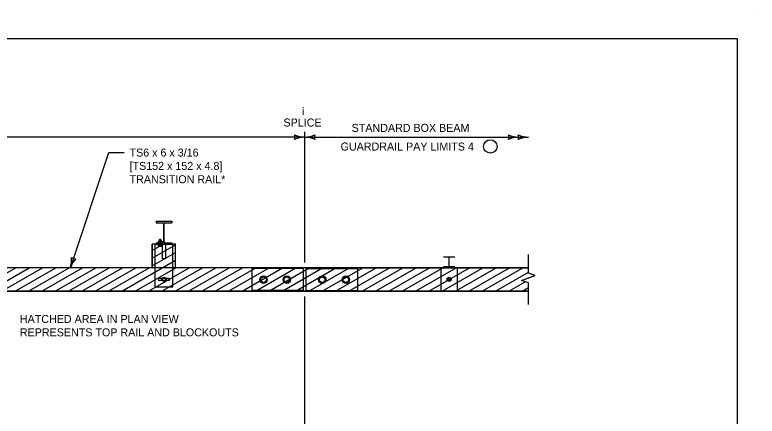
# Model space of a CAD drawing. Extents: x 49983 to 50021, y 49963.5 to 50011.4.
# Drawn here: x 50011.34 to 50016.9, y 49996.17 to 49999.18 of the extents above; entities that cross this region are included whole.
import ezdxf

# ---------------------------------------------------------------- set-up
doc = ezdxf.new("R2010")
doc.units = 0
for name, color, linetype in [('Level 1', 7, 'Continuous'), ('Level 10', 7, 'Continuous'), ('Level 2', 7, 'Continuous'), ('Level 3', 7, 'Continuous'), ('Level 4', 7, 'Continuous'), ('Level 6', 7, 'Continuous')]:
    doc.layers.add(name, color=color, linetype=linetype)

msp = doc.modelspace()

# ---------------------------------------------------------------- linework, layer by layer
at = {"layer": 'Level 1'}
for p, q in [((50016.9001, 49999.1756), (50016.9001, 49999.1756)), ((50012.3959, 49997.6277), (50012.513, 49997.6277)), ((50012.3959, 49997.6277), (50012.3959, 49997.6167)), ((50012.3959, 49997.6167), (50012.4436, 49997.6167)), ((50012.4517, 49997.6098), (50012.4517, 49997.4735)), ((50012.4572, 49997.4734), (50012.4572, 49997.6098)), ((50012.4653, 49997.6167), (50012.513, 49997.6167)), ((50012.513, 49997.6277), (50012.513, 49997.6167)), ((50012.433, 49997.4816), (50012.4199, 49997.4816)), ((50012.4203, 49997.4888), (50012.4216, 49997.49)), ((50012.4203, 49997.4888), (50012.4325, 49997.4888)), ((50012.4203, 49997.4888), (50012.4203, 49997.4816)), ((50012.4313, 49997.49), (50012.4216, 49997.49)), ((50012.4307, 49997.487), (50012.4222, 49997.487)), ((50012.4307, 49997.4857), (50012.4222, 49997.4857)), ((50012.4307, 49997.4845), (50012.4222, 49997.4845)), ((50012.4307, 49997.4833), (50012.4222, 49997.4833)), ((50012.4325, 49997.4888), (50012.4313, 49997.49)), ((50012.4325, 49997.4888), (50012.4325, 49997.4816)), ((50012.3666, 49997.2799), (50012.3666, 49997.4556)), ((50012.5423, 49997.4556), (50012.3666, 49997.4556)), ((50012.3666, 49997.4085), (50012.4482, 49997.4556)), ((50012.3666, 49997.3508), (50012.5423, 49997.4522)), ((50012.3959, 49997.4666), (50012.3959, 49997.4556)), ((50012.3959, 49997.4666), (50012.4436, 49997.4666)), ((50012.3959, 49997.4556), (50012.513, 49997.4556)), ((50012.4452, 49997.471), (50012.4079, 49997.471)), ((50012.4079, 49997.471), (50012.4079, 49997.4666)), ((50012.4133, 49997.4796), (50012.4133, 49997.473)), ((50012.4264, 49997.473), (50012.4264, 49997.4796)), ((50012.4396, 49997.4796), (50012.4396, 49997.473)), ((50012.4452, 49997.471), (50012.4452, 49997.4666)), ((50012.4652, 49997.4666), (50012.513, 49997.4666)), ((50012.513, 49997.4666), (50012.513, 49997.4556)), ((50012.513, 49997.4666), (50012.513, 49997.4556)), ((50012.5423, 49997.2799), (50012.5423, 49997.4556)), ((50012.3666, 49997.293), (50012.5423, 49997.3945)), ((50012.1396, 49997.1042), (50012.5423, 49997.3367)), ((50014.5484, 49997.3606), (50014.6342, 49997.3606)), ((50014.5921, 49997.2896), (50014.5921, 49997.3606)), ((50013.5013, 49997.2799), (50006.3204, 49997.2799)), ((50011.0396, 49997.1042), (50011.3439, 49997.2799)), ((50011.1396, 49997.1042), (50011.4439, 49997.2799)), ((50011.2396, 49997.1042), (50011.5439, 49997.2799)), ((50011.3396, 49997.1042), (50011.6439, 49997.2799)), ((50011.4396, 49997.1042), (50011.7439, 49997.2799)), ((50011.5396, 49997.1042), (50011.8439, 49997.2799)), ((50011.6396, 49997.1042), (50011.9439, 49997.2799)), ((50011.7396, 49997.1042), (50012.0439, 49997.2799)), ((50011.8396, 49997.1042), (50012.1439, 49997.2799)), ((50011.9396, 49997.1042), (50012.2439, 49997.2799)), ((50012.0396, 49997.1042), (50012.3439, 49997.2799)), ((50012.2396, 49997.1042), (50012.5439, 49997.2799)), ((50012.3396, 49997.1042), (50012.6439, 49997.2799)), ((50012.3886, 49997.2799), (50012.3666, 49997.2799)), ((50012.5203, 49997.2799), (50012.3886, 49997.2799)), ((50012.4396, 49997.1042), (50012.7439, 49997.2799)), ((50012.5423, 49997.2799), (50012.5203, 49997.2799)), ((50012.5396, 49997.1042), (50012.8439, 49997.2799)), ((50012.6396, 49997.1042), (50012.9439, 49997.2799)), ((50012.7396, 49997.1042), (50013.0439, 49997.2799)), ((50012.8396, 49997.1042), (50013.1439, 49997.2799)), ((50012.9396, 49997.1042), (50013.2439, 49997.2799)), ((50013.0396, 49997.1042), (50013.3439, 49997.2799)), ((50013.1396, 49997.1042), (50013.4439, 49997.2799)), ((50013.2396, 49997.1042), (50013.5439, 49997.2799)), ((50013.3396, 49997.1042), (50013.6439, 49997.2799)), ((50013.4396, 49997.1042), (50013.7439, 49997.2799)), ((50013.5013, 49997.1042), (50013.5013, 49997.2799)), ((50013.5178, 49997.2799), (50013.5013, 49997.2799)), ((50013.5178, 49997.2799), (50013.5178, 49997.1042)), ((50013.5178, 49997.2799), (50015.1856, 49997.2799)), ((50013.5396, 49997.1042), (50013.8439, 49997.2799)), ((50013.6396, 49997.1042), (50013.9439, 49997.2799)), ((50013.7396, 49997.1042), (50014.0439, 49997.2799)), ((50013.8396, 49997.1042), (50014.1439, 49997.2799)), ((50013.9396, 49997.1042), (50014.2439, 49997.2799)), ((50014.0396, 49997.1042), (50014.3439, 49997.2799)), ((50014.1396, 49997.1042), (50014.4439, 49997.2799)), ((50014.2396, 49997.1042), (50014.5439, 49997.2799)), ((50014.3396, 49997.1042), (50014.6439, 49997.2799)), ((50014.4396, 49997.1042), (50014.7439, 49997.2799)), ((50014.5335, 49997.2799), (50014.6506, 49997.2799)), ((50014.5396, 49997.1042), (50014.8439, 49997.2799)), ((50014.5484, 49997.2896), (50014.6342, 49997.2896)), ((50014.6396, 49997.1042), (50014.9439, 49997.2799)), ((50014.7396, 49997.1042), (50015.0439, 49997.2799)), ((50014.8396, 49997.1042), (50015.1439, 49997.2799)), ((50012.4436, 49997.1985), (50012.4548, 49997.2049)), ((50012.4548, 49997.2049), (50012.4659, 49997.1985)), ((50013.1811, 49997.2021), (50013.2013, 49997.2134)), ((50013.2013, 49997.2134), (50013.2205, 49997.2021)), ((50013.3565, 49997.2021), (50013.3766, 49997.2134)), ((50013.3766, 49997.2134), (50013.3958, 49997.2021)), ((50013.6214, 49997.2021), (50013.6415, 49997.2134)), ((50013.6415, 49997.2134), (50013.6608, 49997.2021)), ((50013.7982, 49997.2021), (50013.8183, 49997.2134)), ((50013.8183, 49997.2134), (50013.8375, 49997.2021)), ((50014.5811, 49997.1985), (50014.5923, 49997.2049)), ((50014.5923, 49997.2049), (50014.6033, 49997.1985)), ((50014.9396, 49997.1042), (50015.1855, 49997.2462)), ((50012.4436, 49997.1857), (50012.4436, 49997.1985)), ((50012.4548, 49997.1793), (50012.4436, 49997.1857)), ((50012.4659, 49997.1857), (50012.4548, 49997.1793)), ((50012.4659, 49997.1985), (50012.4659, 49997.1857)), ((50013.1811, 49997.1787), (50013.1811, 49997.2021)), ((50013.2013, 49997.1675), (50013.1811, 49997.1787)), ((50013.2205, 49997.1787), (50013.2013, 49997.1675)), ((50013.2205, 49997.2021), (50013.2205, 49997.1787)), ((50013.3565, 49997.1787), (50013.3565, 49997.2021)), ((50013.3766, 49997.1675), (50013.3565, 49997.1787)), ((50013.3958, 49997.1787), (50013.3766, 49997.1675)), ((50013.3958, 49997.2021), (50013.3958, 49997.1787)), ((50013.6214, 49997.1787), (50013.6214, 49997.2021)), ((50013.6415, 49997.1675), (50013.6214, 49997.1787)), ((50013.6608, 49997.1787), (50013.6415, 49997.1675)), ((50013.6608, 49997.2021), (50013.6608, 49997.1787)), ((50013.7982, 49997.1787), (50013.7982, 49997.2021)), ((50013.8183, 49997.1675), (50013.7982, 49997.1787)), ((50013.8375, 49997.1787), (50013.8183, 49997.1675)), ((50013.8375, 49997.2021), (50013.8375, 49997.1787)), ((50014.5811, 49997.1857), (50014.5811, 49997.1985)), ((50014.5923, 49997.1793), (50014.5811, 49997.1857)), ((50014.6033, 49997.1857), (50014.5923, 49997.1793)), ((50014.6033, 49997.1985), (50014.6033, 49997.1857)), ((50015.0396, 49997.1042), (50015.162, 49997.1749)), ((50013.5013, 49997.1042), (50005.4468, 49997.1042)), ((50013.5178, 49997.1042), (50013.5013, 49997.1042)), ((50015.1856, 49997.1042), (50013.5178, 49997.1042)), ((50015.1396, 49997.1042), (50015.1855, 49997.1308))]:
    msp.add_line(p, q, dxfattribs=at)
msp.add_lwpolyline([(49999.3835, 49998.9992), (50016.7501, 49998.9992), (50016.7501, 49987.7988), (49999.3835, 49987.7988)], close=True, dxfattribs=at)
for points in [[(50006.7444, 49997.2799), (50006.3204, 49997.2799), (50006.3204, 49997.456), (50003.275, 49997.456), (50003.275, 49997.2799), (50003.2457, 49997.2799), (50002.2562, 49997.4473), (50002.2558, 49997.4447), (50002.2559, 49997.452), (50001.5623, 49997.4576), (50001.5622, 49997.4503), (50001.7737, 49997.3496), (50002.2274, 49997.2739), (50003.2457, 49997.1042), (50005.4468, 49997.1042), (50005.4633, 49997.1042), (50015.1856, 49997.1042), (50015.1855, 49997.1666), (50015.1344, 49997.1847), (50015.2365, 49997.2209), (50015.1855, 49997.239), (50015.1855, 49997.2799), (50012.5423, 49997.2799)], [(50012.5423, 49997.2799), (50012.5423, 49997.4556), (50012.3666, 49997.4556), (50012.3666, 49997.2799)], [(50012.3666, 49997.2799), (50010.434, 49997.2799)]]:
    msp.add_lwpolyline(points, dxfattribs=at)
for centre, radius in [((50012.4546, 49997.1921), 0.0155), ((50013.2006, 49997.1904), 0.0279), ((50013.3759, 49997.1904), 0.0279), ((50013.6409, 49997.1904), 0.0279), ((50013.8176, 49997.1904), 0.0279), ((50014.5921, 49997.1921), 0.0155)]:
    msp.add_circle(centre, radius, dxfattribs=at)
for centre, radius, start, end in [((50012.4442, 49997.6092), 0.00746, 4.5337, 94.5337), ((50012.4647, 49997.6092), 0.00752, 85.0809, 175.0809), ((50012.4199, 49997.47), 0.0116, 55.616, 124.384), ((50012.433, 49997.47), 0.0116, 55.616, 124.384), ((50012.4199, 49997.4826), 0.0116, 235.616, 304.384), ((50012.433, 49997.4826), 0.0116, 235.616, 304.384), ((50012.4442, 49997.4741), 0.00753, 265.5645, 355.5652), ((50012.4646, 49997.474), 0.00741, 184.3799, 274.3799)]:
    msp.add_arc(centre, radius, start, end, dxfattribs=at)
at = {"layer": 'Level 10'}
for p, q in [((50012.4203, 49997.4512), (50012.4203, 49997.4816)), ((50012.4325, 49997.4512), (50012.4325, 49997.4816)), ((50012.3886, 49997.1335), (50012.3886, 49997.4556)), ((50012.4079, 49997.4512), (50012.4079, 49997.4556)), ((50012.4452, 49997.4512), (50012.4079, 49997.4512)), ((50012.4133, 49997.4414), (50012.4133, 49997.4512)), ((50012.433, 49997.4406), (50012.4199, 49997.4406)), ((50012.4264, 49997.4414), (50012.4264, 49997.4512)), ((50012.4396, 49997.4414), (50012.4396, 49997.4512)), ((50012.4435, 49997.3466), (50012.4435, 49997.4556)), ((50012.4452, 49997.4512), (50012.4452, 49997.4556)), ((50012.4654, 49997.4556), (50012.4654, 49997.3466)), ((50012.5203, 49997.1335), (50012.5203, 49997.4556)), ((50012.4654, 49997.3466), (50012.4435, 49997.3466)), ((50013.5014, 49997.2731), (50013.1139, 49997.2731)), ((50013.5178, 49997.2731), (50013.9048, 49997.2731)), ((50014.5331, 49997.1042), (50014.5331, 49997.2799)), ((50014.6522, 49997.2799), (50014.6522, 49997.1042)), ((50012.4912, 49997.1994), (50012.418, 49997.1994)), ((50012.4912, 49997.1848), (50012.418, 49997.1848)), ((50012.5203, 49997.1335), (50012.3886, 49997.1335)), ((50013.5014, 49997.1077), (50013.1139, 49997.1077)), ((50013.5178, 49997.1077), (50013.9048, 49997.1077))]:
    msp.add_line(p, q, dxfattribs=at)
for centre, radius, start, end in [((50012.4199, 49997.4682), 0.0276, 256.2307, 283.7693), ((50012.433, 49997.4682), 0.0276, 256.2307, 283.7693), ((50012.418, 49997.1921), 0.00731, 90, 270), ((50012.4912, 49997.1921), 0.00731, 270, 90)]:
    msp.add_arc(centre, radius, start, end, dxfattribs=at)
at = {"layer": 'Level 2'}
msp.add_circle((50014.9008, 49998.1886), 0.0503, dxfattribs=at)
at = {"layer": 'Level 3'}
for p, q in [((50013.5095, 49997.32), (50013.5096, 49998.2981)), ((50013.5096, 49998.2581), (50005.0789, 49998.2581)), ((50013.5096, 49998.2581), (50015.1855, 49998.2581)), ((50011.7533, 49997.2799), (50012.0407, 49998.1429)), ((50012.0407, 49998.1429), (50012.1568, 49998.1429)), ((50013.5096, 49995.3262), (50013.5096, 49997.0642))]:
    msp.add_line(p, q, dxfattribs=at)
for centre, radius, start, end in [((50013.5188, 49998.4802), 0.2223, 247.456, 267.6395), ((50013.3814, 49998.2581), 0.0548, 342.1388, 17.8612), ((50013.4981, 49998.4908), 0.233, 272.8273, 292.0772), ((50013.6378, 49998.2581), 0.0548, 162.1388, 197.8612), ((50015.1212, 49998.4802), 0.2223, 247.456, 267.6395), ((50014.9838, 49998.2581), 0.0548, 342.1388, 17.8612), ((50015.1946, 49998.4802), 0.2223, 247.456, 267.6395), ((50015.0573, 49998.2581), 0.0548, 342.1388, 17.8612), ((50013.5211, 49998.0254), 0.233, 92.8273, 112.0772), ((50013.5004, 49998.0359), 0.2223, 67.456, 87.6395), ((50015.1235, 49998.0254), 0.233, 92.8273, 112.0772), ((50015.197, 49998.0254), 0.233, 92.8273, 112.0772), ((50011.5289, 49997.3425), 0.233, 344.4135, 3.6633), ((50011.9612, 49997.2011), 0.2223, 139.0422, 159.2257), ((50011.7938, 49997.4016), 0.0548, 233.725, 269.4473)]:
    msp.add_arc(centre, radius, start, end, dxfattribs=at)
at = {"layer": 'Level 4'}
for p, q in [((50013.1139, 49997.2799), (50013.1139, 49997.1042)), ((50013.9048, 49997.2799), (50013.9048, 49997.1042))]:
    msp.add_line(p, q, dxfattribs=at)
at = {"layer": 'Level 6'}
for p, q in [((50015.1855, 49997.239), (50015.1855, 49997.3799)), ((50015.1344, 49997.1847), (50015.1855, 49997.2029)), ((50015.2365, 49997.2209), (50015.1855, 49997.239)), ((50015.1855, 49997.2029), (50015.2365, 49997.2209)), ((50015.1855, 49997.1666), (50015.1344, 49997.1847)), ((50015.1855, 49997.0042), (50015.1855, 49997.1666))]:
    msp.add_line(p, q, dxfattribs=at)

# ---------------------------------------------------------------- texts
at = {"layer": 'Level 2'}
for s, p in [('¡', (50013.4845, 49998.4381)), ('SPLICE', (50013.3506, 49998.3381)), ('STANDARD BOX BEAM', (50013.8611, 49998.2981)), ('GUARDRAIL PAY LIMITS 4', (50013.7785, 49998.1581)), ('TS6 x 6 x 3/16', (50012.1968, 49998.1129)), ('[TS152 x 152 x 4.8]', (50012.1968, 49998.0129)), ('TRANSITION RAIL*', (50012.1968, 49997.9129)), ('HATCHED AREA IN PLAN VIEW', (50011.3749, 49996.8652)), ('REPRESENTS TOP RAIL AND BLOCKOUTS', (50011.3749, 49996.7652))]:
    msp.add_text(s, height=0.06, dxfattribs=at).set_placement(p)

doc.saveas('drawing.dxf')
